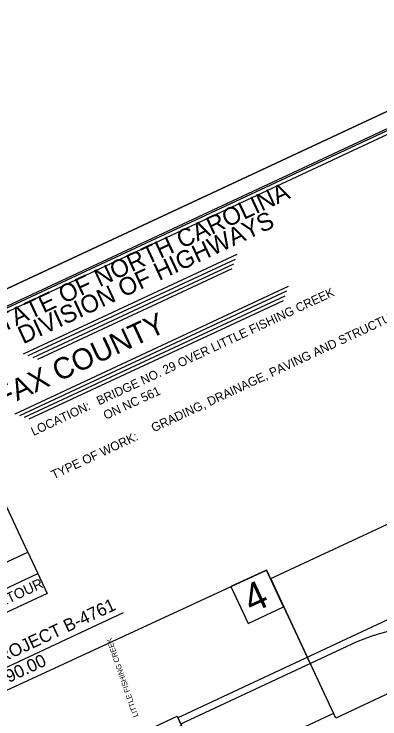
# Model space of a CAD drawing. Extents: x 2318983 to 2324558, y 920396 to 924651.
# Drawn here: x 2321231 to 2322471, y 922262 to 924651 of the extents above; entities that cross this region are included whole.
import ezdxf

# ---------------------------------------------------------------- set-up
doc = ezdxf.new("R2010")
doc.units = 0
for name, color, linetype in [('Old_Level_1', 7, 'Continuous'), ('Pattern 3', 7, 'Continuous'), ('Prop Dimension', 7, 'Continuous'), ('Prop DSN Text', 7, 'Continuous'), ('Prop Shade Light', 7, 'Continuous'), ('Prop Shade Medium', 7, 'Continuous'), ('Sheet Cutting Line CELL', 7, 'Continuous'), ('Sheet Data Field CELL', 7, 'Continuous'), ('Sheet Plot Border Inside CELL', 7, 'Continuous'), ('Sheet Plot Border Outside CELL', 7, 'Continuous'), ('Sheet Title CELL', 7, 'Continuous'), ('Sheet Title Data Points CELL', 7, 'Continuous')]:
    doc.layers.add(name, color=color, linetype=linetype)

msp = doc.modelspace()

# ---------------------------------------------------------------- linework, layer by layer
at = {"layer": 'Pattern 3'}
for p, q in [((2321276.8, 922827.5), (2320981.8, 923459.5)), ((2320435.7, 922346.1), (2321310.8, 922754.5))]:
    msp.add_line(p, q, dxfattribs=at)
msp.add_lwpolyline([(2320401.7, 922419.1), (2321276.8, 922827.5), (2321342.3, 922687.1), (2320467.2, 922278.7)], close=True, dxfattribs=at)
at = {"layer": 'Prop Dimension'}
for p, q in [((2322100.4, 922737.9), (2323278.1, 923286)), ((2323496.8, 922818), (2322321.6, 922264.7)), ((2320815.9, 922178.3), (2322085.9, 922766.6)), ((2322085.9, 922766.6), (2322313.3, 922280)), ((2322321.6, 922264.7), (2322100.4, 922737.9)), ((2322313.3, 922280), (2321040.8, 921692.7))]:
    msp.add_line(p, q, dxfattribs=at)
msp.add_lwpolyline([(2322085.9, 922766.6), (2321965.8, 922710.5), (2322024.3, 922585.2), (2322144.3, 922641.3)], close=True, dxfattribs=at)
at = {"layer": 'Prop DSN Text'}
msp.add_line((2320871.1, 922281.4), (2321601.6, 922622.3), dxfattribs=at)
at = {"layer": 'Prop Shade Light'}
msp.add_lwpolyline([(2321795.7, 922244.4), (2321785.6, 922266.1), (2321799.3, 922272.5), (2322514, 922606.4), (2322532.6, 922566.6), (2322520.8, 922563.9), (2322506.2, 922560.4), (2322484.7, 922554.6), (2322461.3, 922548), (2322451.7, 922545.1), (2322448.3, 922544.1), (2322446, 922543.4), (2322439.7, 922541.4), (2322439.7, 922541.4), (2322439.7, 922541.4), (2322392.8, 922523.2), (2321809.5, 922250.8)], close=True, dxfattribs=at)
at = {"layer": 'Prop Shade Medium'}
msp.add_lwpolyline([(2321607.5, 922151.1), (2321593.1, 922181.9), (2321783.4, 922270.7), (2321797.8, 922239.8)], close=True, dxfattribs=at)
at = {"layer": 'Sheet Cutting Line CELL'}
msp.add_line((2319538.3, 922942), (2323200.7, 924651.2), dxfattribs=at)
at = {"layer": 'Sheet Plot Border Inside CELL'}
msp.add_lwpolyline([(2320660.3, 920611.7), (2324284.6, 922303.2), (2323213.7, 924597.8), (2319589.4, 922906.3)], close=True, dxfattribs=at)
at = {"layer": 'Sheet Plot Border Outside CELL'}
msp.add_lwpolyline([(2323200.7, 924651.2), (2319538.3, 922942), (2320654.8, 920549.7), (2324317.2, 922258.9)], close=True, dxfattribs=at)
at = {"layer": 'Sheet Title CELL'}
for p, q in [((2321263.1, 923499.1), (2321986.7, 923836.9)), ((2321279, 923493.4), (2321980.9, 923820.9)), ((2321295, 923487.5), (2321975.1, 923805)), ((2321310.9, 923481.7), (2321969.3, 923789.1)), ((2321234.3, 923296.1), (2322160.8, 923728.5)), ((2321250.2, 923290.3), (2322155, 923712.5)), ((2321266.2, 923284.5), (2322149.1, 923696.6)), ((2321282.1, 923278.7), (2322143.4, 923680.6))]:
    msp.add_line(p, q, dxfattribs=at)
for points in [[(2323167.4, 924569.4), (2319948.6, 923067.3)], [(2323161.6, 924553.5), (2320073.4, 923112.2)]]:
    msp.add_lwpolyline(points, dxfattribs=at)
at = {"layer": 'Sheet Title Data Points CELL'}
for p, q in [((2322002, 923549.9), (2322002, 923549.9)), ((2321685.8, 923546.3), (2321685.8, 923546.3))]:
    msp.add_line(p, q, dxfattribs=at)

# ---------------------------------------------------------------- texts
at = {"layer": 'Old_Level_1'}
msp.add_text('LITTLE FISHING CREEK', height=18, rotation=109.0356, dxfattribs=at).set_placement((2321652.4, 922271.2))
at = {"layer": 'Pattern 3'}
msp.add_text('DENOTES OFF-SITE DETOUR', height=34.8, rotation=25.0187, dxfattribs=at).set_placement((2320735.8, 922429.9))
at = {"layer": 'Prop DSN Text'}
for s, height, rotation, p in [('4', 96, 24.9913, (2322036, 922618.2)), ('BEGIN TIP PROJECT B-4761', 43.2, 25.0187, (2320878.2, 922306.1)), ('-L- STA. 12+90.00', 43.2, 25.0187, (2320914.9, 922244.4))]:
    msp.add_text(s, height=height, rotation=rotation, dxfattribs=at).set_placement(p)
at = {"layer": 'Sheet Data Field CELL'}
for s, height, p in [('BRIDGE NO. 29 OVER LITTLE FISHING CREEK ', 30, (2321518.9, 923324.5)), ('GRADING, DRAINAGE, PAVING AND STRUCTURE ', 30, (2321704, 923233.3)), ('        HALIFAX COUNTY       ', 72, (2320799.8, 923132.8)), ('ON NC 561                               ', 30, (2321541.8, 923275.5))]:
    msp.add_text(s, height=height, rotation=25.0187, dxfattribs=at).set_placement(p)
at = {"layer": 'Sheet Title CELL'}
for s, height, p in [('STATE OF NORTH CAROLINA', 60, (2321144.7, 923549.7)), ('DIVISION OF HIGHWAYS', 60, (2321261.5, 923531.4)), ('LOCATION: ', 30, (2321296.5, 923220.7)), ('TYPE OF WORK:', 30, (2321365, 923073.8))]:
    msp.add_text(s, height=height, rotation=25.0187, dxfattribs=at).set_placement(p)

doc.saveas('drawing.dxf')
